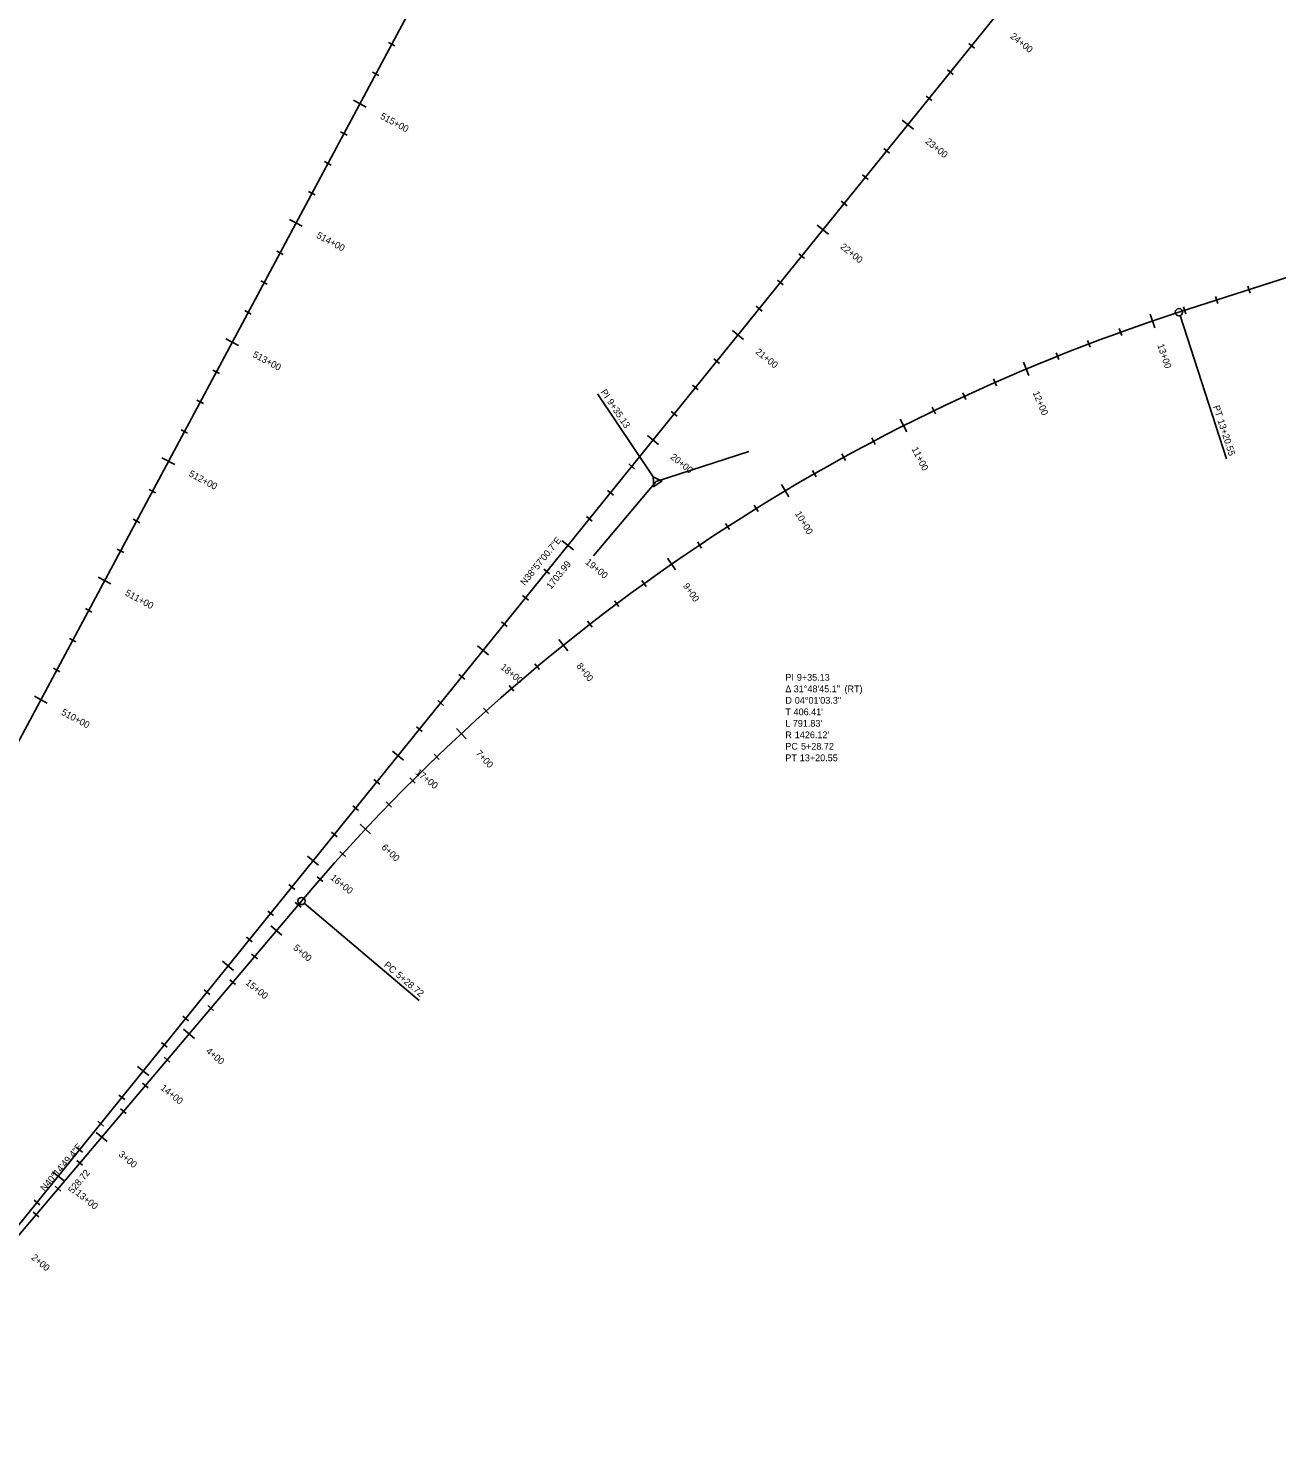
# Model space of a CAD drawing. Extents: x 2300830 to 2307917, y 756066 to 766359.
# Drawn here: x 2302821 to 2303744, y 759600 to 760655 of the extents above; entities that cross this region are included whole.
import ezdxf

# ---------------------------------------------------------------- set-up
doc = ezdxf.new("R2010")
doc.units = 0
for name, color, linetype in [('Default', 7, 'Continuous'), ('Draft_Bearing Label', 7, 'Continuous'), ('Draft_Curve Data Label', 7, 'Continuous'), ('Draft_Station Cardinal Lines', 7, 'Continuous'), ('Draft_Station Cardinal Points', 7, 'Continuous'), ('Draft_Station Labels Major', 7, 'Continuous'), ('Draft_Station Ticks Major', 7, 'Continuous'), ('Draft_Station Ticks Minor', 7, 'Continuous'), ('Geom_Baseline', 7, 'Continuous')]:
    doc.layers.add(name, color=color, linetype=linetype)

msp = doc.modelspace()

# ---------------------------------------------------------------- linework, layer by layer
at = {"layer": 'Default'}
for p, q in [((2301469, 757616.6), (2303797.1, 761965)), ((2301469, 757616.6), (2303797.1, 761965)), ((2302671.5, 759594.4), (2303742.7, 760919.6)), ((2303672.3, 760445.6), (2304246.1, 760631.4)), ((2302681.5, 759606.7), (2303023.1, 760010.2))]:
    msp.add_line(p, q, dxfattribs=at)
msp.add_arc((2304111.6, 759088.8), 1426.1, 107.9404, 139.7529, dxfattribs=at)
at = {"layer": 'Draft_Station Cardinal Lines'}
for p, q in [((2303673.1, 760443.1), (2303707.4, 760337.2)), ((2303283.3, 760323.9), (2303242.2, 760385.2)), ((2303285.6, 760320.4), (2303354.1, 760342.6)), ((2303285.6, 760320.4), (2303239.1, 760265.5)), ((2303025.1, 760008.5), (2303110.1, 759936.6))]:
    msp.add_line(p, q, dxfattribs=at)
msp.add_lwpolyline([(2303283.3, 760323.9), (2303283.8, 760316.7), (2303289.8, 760320.7)], close=True, dxfattribs=at)
at = {"layer": 'Draft_Station Cardinal Points'}
for p, q in [((2303672.3, 760445.6), (2303672.3, 760445.6)), ((2303242.2, 760385.2), (2303242.2, 760385.2)), ((2303707.4, 760337.2), (2303707.4, 760337.2)), ((2303285.6, 760320.4), (2303285.6, 760320.4)), ((2303023.1, 760010.2), (2303023.1, 760010.2)), ((2303110.1, 759936.6), (2303110.1, 759936.6))]:
    msp.add_line(p, q, dxfattribs=at)
for centre in [(2303672.3, 760445.6), (2303023.1, 760010.2)]:
    msp.add_circle(centre, 2.67, dxfattribs=at)
at = {"layer": 'Draft_Station Ticks Major'}
for p, q in [((2303061.5, 760602.4), (2303070.9, 760597.3)), ((2303467.6, 760587.7), (2303475.9, 760581)), ((2303014.3, 760514.2), (2303023.7, 760509.2)), ((2303404.7, 760510), (2303413, 760503.3)), ((2303651.1, 760444.2), (2303654.5, 760434.2)), ((2303341.9, 760432.2), (2303350.1, 760425.5)), ((2302967.1, 760426), (2302976.5, 760421)), ((2303557.2, 760408.6), (2303561.3, 760398.8)), ((2303466.1, 760366.5), (2303470.9, 760357.1)), ((2303279, 760354.4), (2303287.3, 760347.7)), ((2302919.9, 760337.9), (2302929.3, 760332.9)), ((2303378.2, 760318.2), (2303383.6, 760309.1)), ((2303216.1, 760276.6), (2303224.4, 760270)), ((2303293.9, 760263.8), (2303299.9, 760255.1)), ((2302872.7, 760249.7), (2302882.1, 760244.7)), ((2303153.3, 760198.9), (2303161.5, 760192.2)), ((2303213.6, 760203.6), (2303220.2, 760195.3)), ((2302825.5, 760161.6), (2302834.9, 760156.5)), ((2303137.7, 760137.9), (2303144.9, 760130.2)), ((2303090.4, 760121.1), (2303098.7, 760114.4)), ((2303066.5, 760067.1), (2303074.3, 760059.9)), ((2303027.6, 760043.3), (2303035.8, 760036.7)), ((2303000.4, 759991.8), (2303008.5, 759984.9)), ((2302964.7, 759965.6), (2302972.9, 759958.9)), ((2302935.8, 759915.4), (2302943.9, 759908.6)), ((2302901.8, 759887.8), (2302910.1, 759881.1)), ((2302871.2, 759839.1), (2302879.3, 759832.3)), ((2302839, 759810), (2302847.2, 759803.4))]:
    msp.add_line(p, q, dxfattribs=at)
at = {"layer": 'Draft_Station Ticks Minor'}
for p, q in [((2303087.4, 760645.2), (2303092.2, 760642.6)), ((2303516.8, 760644.4), (2303521.1, 760641)), ((2303075.6, 760623.2), (2303080.4, 760620.6)), ((2303501, 760625), (2303505.3, 760621.5)), ((2303485.3, 760605.5), (2303489.6, 760602.1)), ((2303052, 760579.1), (2303056.8, 760576.5)), ((2303453.9, 760566.7), (2303458.2, 760563.2)), ((2303040.2, 760557.1), (2303045, 760554.5)), ((2303438.2, 760547.2), (2303442.5, 760543.7)), ((2303028.4, 760535), (2303033.2, 760532.4)), ((2303422.5, 760527.8), (2303426.8, 760524.3)), ((2303004.8, 760490.9), (2303009.6, 760488.3)), ((2303391, 760488.9), (2303395.3, 760485.4)), ((2302993, 760468.9), (2302997.8, 760466.3)), ((2303375.3, 760469.4), (2303379.6, 760466)), ((2303723.2, 760465), (2303724.9, 760459.8)), ((2303359.6, 760450), (2303363.9, 760446.5)), ((2303675.7, 760449.6), (2303677.4, 760444.4)), ((2303699.4, 760457.3), (2303701.1, 760452.1)), ((2302981.2, 760446.9), (2302986, 760444.3)), ((2303628.2, 760433.5), (2303630.1, 760428.3)), ((2303604.7, 760424.8), (2303606.7, 760419.7)), ((2303328.2, 760411.1), (2303332.5, 760407.7)), ((2303581.4, 760415.7), (2303583.5, 760410.6)), ((2302957.6, 760402.8), (2302962.4, 760400.2)), ((2303312.5, 760391.7), (2303316.7, 760388.2)), ((2303512.4, 760386), (2303514.7, 760381)), ((2303535.2, 760396.3), (2303537.4, 760391.3)), ((2302945.8, 760380.7), (2302950.6, 760378.1)), ((2303296.7, 760372.2), (2303301, 760368.8)), ((2303489.7, 760375.3), (2303492.1, 760370.4)), ((2302934, 760358.7), (2302938.8, 760356.1)), ((2303445, 760352.7), (2303447.6, 760347.9)), ((2303265.3, 760333.4), (2303269.6, 760329.9)), ((2303423, 760340.9), (2303425.6, 760336)), ((2303401.1, 760328.6), (2303403.9, 760323.8)), ((2302910.4, 760314.6), (2302915.2, 760312)), ((2303249.6, 760313.9), (2303253.9, 760310.4)), ((2303358.1, 760302.9), (2303361, 760298.2)), ((2302898.6, 760292.6), (2302903.4, 760290)), ((2303233.9, 760294.5), (2303238.2, 760291)), ((2303336.9, 760289.5), (2303339.9, 760284.9)), ((2302886.8, 760270.5), (2302891.6, 760267.9)), ((2303316, 760275.8), (2303319.1, 760271.2)), ((2303202.4, 760255.6), (2303206.7, 760252.1)), ((2303274.9, 760247.2), (2303278.1, 760242.7)), ((2303186.7, 760236.1), (2303191, 760232.7)), ((2303254.7, 760232.3), (2303258, 760227.9)), ((2302863.2, 760226.5), (2302868, 760223.9)), ((2303234.8, 760217.1), (2303238.2, 760212.8)), ((2303171, 760216.7), (2303175.3, 760213.2)), ((2302851.4, 760204.4), (2302856.2, 760201.8)), ((2303195.8, 760185.7), (2303199.3, 760181.5)), ((2302839.6, 760182.4), (2302844.4, 760179.8)), ((2303139.6, 760177.8), (2303143.9, 760174.3)), ((2303176.7, 760169.5), (2303180.3, 760165.3)), ((2303123.9, 760158.4), (2303128.2, 760154.9)), ((2303157.9, 760152.9), (2303161.6, 760148.8)), ((2303108.1, 760138.9), (2303112.4, 760135.5)), ((2303121.2, 760118.8), (2303125, 760114.9)), ((2303103.3, 760101.3), (2303107.2, 760097.4)), ((2303076.7, 760100), (2303081, 760096.6)), ((2303061, 760080.6), (2303065.3, 760077.1)), ((2303085.7, 760083.5), (2303089.7, 760079.7)), ((2303045.3, 760061.2), (2303049.6, 760057.7)), ((2303051.5, 760046.9), (2303055.6, 760043.2)), ((2303034.8, 760028.2), (2303039, 760024.6)), ((2303013.8, 760022.3), (2303018.1, 760018.8)), ((2303018.5, 760009.2), (2303022.8, 760005.6)), ((2302998.1, 760002.8), (2303002.4, 759999.4)), ((2302982.4, 759983.4), (2302986.7, 759979.9)), ((2302986.2, 759971), (2302990.5, 759967.5)), ((2302951, 759944.5), (2302955.3, 759941)), ((2302970.1, 759951.9), (2302974.3, 759948.4)), ((2302953.9, 759932.9), (2302958.1, 759929.3)), ((2302935.3, 759925.1), (2302939.6, 759921.6)), ((2302919.5, 759905.6), (2302923.8, 759902.1)), ((2302921.6, 759894.7), (2302925.8, 759891.1)), ((2302905.5, 759875.6), (2302909.7, 759872)), ((2302888.1, 759866.7), (2302892.4, 759863.3)), ((2302889.3, 759856.5), (2302893.5, 759853)), ((2302872.4, 759847.3), (2302876.7, 759843.8)), ((2302856.7, 759827.9), (2302861, 759824.4)), ((2302857, 759818.4), (2302861.2, 759814.8)), ((2302840.9, 759799.3), (2302845.1, 759795.7)), ((2302825.3, 759789), (2302829.5, 759785.5)), ((2302824.7, 759780.2), (2302828.9, 759776.6))]:
    msp.add_line(p, q, dxfattribs=at)
at = {"layer": 'Geom_Baseline'}
for p, q in [((2301469, 757616.6), (2303797.1, 761965)), ((2302671.5, 759594.4), (2303742.7, 760919.6)), ((2303672.3, 760445.6), (2304246.1, 760631.4)), ((2302681.5, 759606.7), (2303023.1, 760010.2))]:
    msp.add_line(p, q, dxfattribs=at)
msp.add_arc((2304111.6, 759088.8), 1426.1, 107.9404, 139.7529, dxfattribs=at)

# ---------------------------------------------------------------- texts
at = {"layer": 'Draft_Bearing Label'}
for s, rotation, p in [('N38°57\'00.7"E', 51.0498, (2303188.4, 760243.1)), ('1703.99', 51.0498, (2303207.7, 760240.4)), ('N40°14\'49.4"E', 49.7529, (2302833.2, 759795.1)), ('528.72', 49.7529, (2302853.8, 759793.4))]:
    msp.add_text(s, height=5, rotation=rotation, dxfattribs=at).set_placement(p)
at = {"layer": 'Draft_Curve Data Label'}
for s, p in [('PI ', (2303381.1, 760173.1)), ('9+35.13', (2303389.6, 760173.1)), ('Δ ', (2303381.1, 760164.6)), ('31°48\'45.1"', (2303387.3, 760164.6)), (' (RT)', (2303423, 760164.6)), ('D ', (2303381.1, 760156.1)), ('04°01\'03.3"', (2303388.1, 760156.1)), ('T ', (2303381.1, 760147.6)), ('L ', (2303381.1, 760139.1)), ("791.83'", (2303386.6, 760139.1)), ("406.41'", (2303387.2, 760147.6)), ('R ', (2303381.1, 760130.6)), ("1426.12'", (2303388.1, 760130.6)), ('PC ', (2303381.1, 760122.1)), ('5+28.72', (2303392.7, 760122.1)), ('PT ', (2303381.1, 760113.6)), ('13+20.55', (2303391.8, 760113.6))]:
    msp.add_text(s, height=5, dxfattribs=at).set_placement(p)
at = {"layer": 'Draft_Station Cardinal Points'}
for s, rotation, p in [('PI ', 303.8467, (2303244.2, 760386.6)), ('9+35.13', 303.8467, (2303249, 760379.5)), ('PT', 287.9404, (2303697.5, 760375.9)), ('13+20.55', 287.9404, (2303700.8, 760365.6)), ('PC', 319.7529, (2303083.6, 759962.2)), ('5+28.72', 319.7529, (2303092.5, 759954.7))]:
    msp.add_text(s, height=5, rotation=rotation, dxfattribs=at).set_placement(p)
at = {"layer": 'Draft_Station Labels Major'}
for s, rotation, p in [('24+00', 321.0498, (2303547.1, 760648.9)), ('515+00', 331.8357, (2303080.9, 760589.1)), ('23+00', 321.0498, (2303484.2, 760571.1)), ('514+00', 331.8357, (2303033.7, 760501)), ('22+00', 321.0498, (2303421.3, 760493.3)), ('21+00', 321.0498, (2303358.5, 760415.6)), ('13+00', 288.766, (2303656.2, 760421.3)), ('513+00', 331.8357, (2302986.5, 760412.8)), ('12+00', 292.7836, (2303564, 760386.1)), ('11+00', 296.8012, (2303474.4, 760344.6)), ('20+00', 321.0498, (2303295.6, 760337.8)), ('512+00', 331.8357, (2302939.3, 760324.7)), ('10+00', 300.8188, (2303388, 760296.8)), ('19+00', 321.0498, (2303232.7, 760260)), ('511+00', 331.8357, (2302892.1, 760236.5)), ('9+00', 304.8363, (2303305.1, 760243.2)), ('8+00', 308.8539, (2303226.2, 760183.8)), ('18+00', 321.0498, (2303169.9, 760182.3)), ('510+00', 331.8357, (2302844.9, 760148.3)), ('7+00', 312.8715, (2303151.7, 760119.1)), ('17+00', 321.0498, (2303107, 760104.5)), ('6+00', 316.8891, (2303081.9, 760049.3)), ('16+00', 321.0498, (2303044.1, 760026.7)), ('5+00', 319.7529, (2303016.6, 759974.8)), ('15+00', 321.0498, (2302981.3, 759949)), ('4+00', 319.7529, (2302952, 759898.5)), ('14+00', 321.0498, (2302918.4, 759871.2)), ('3+00', 319.7529, (2302887.4, 759822.1)), ('13+00', 321.0498, (2302855.5, 759793.4)), ('2+00', 319.7529, (2302822.8, 759745.8))]:
    msp.add_text(s, height=5, rotation=rotation, dxfattribs=at).set_placement(p)

doc.saveas('drawing.dxf')
